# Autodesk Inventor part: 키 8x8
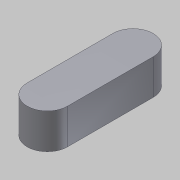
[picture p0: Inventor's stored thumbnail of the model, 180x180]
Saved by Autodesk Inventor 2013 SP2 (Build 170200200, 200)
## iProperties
Company: 한국ATC센터
Created: 2014-11
Part Number: 키 8x8
Document SubType Name: Modeling
Designer: KYOUNG IL JANG
Density: 7.86 g/cm^3
Material: 강, 연강
Mass: 10.2483 g
Surface Area: 7.8646 cm^2
Volume: 1.30386 cm^3
Author: KYOUNG IL JANG
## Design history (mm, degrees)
sketch "스케치1"
  geometry: L1 (28.264, -14)-(28.264, -31) reference; L2 (20.264, -31)-(20.264, -14) reference; A1 r 4 centre (24.264, -31) between (20.264, -31) and (28.264, -31) reference; A2 r 4 centre (24.264, -14) between (28.264, -14) and (20.264, -14) reference; 1 further point
extrude "돌출1" new body sketch "스케치1" distance "d0" = 7; taper "d1" = 0 deg
node "솔리드1"
node "참조1"
